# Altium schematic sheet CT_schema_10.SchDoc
size 278 x 170 mm
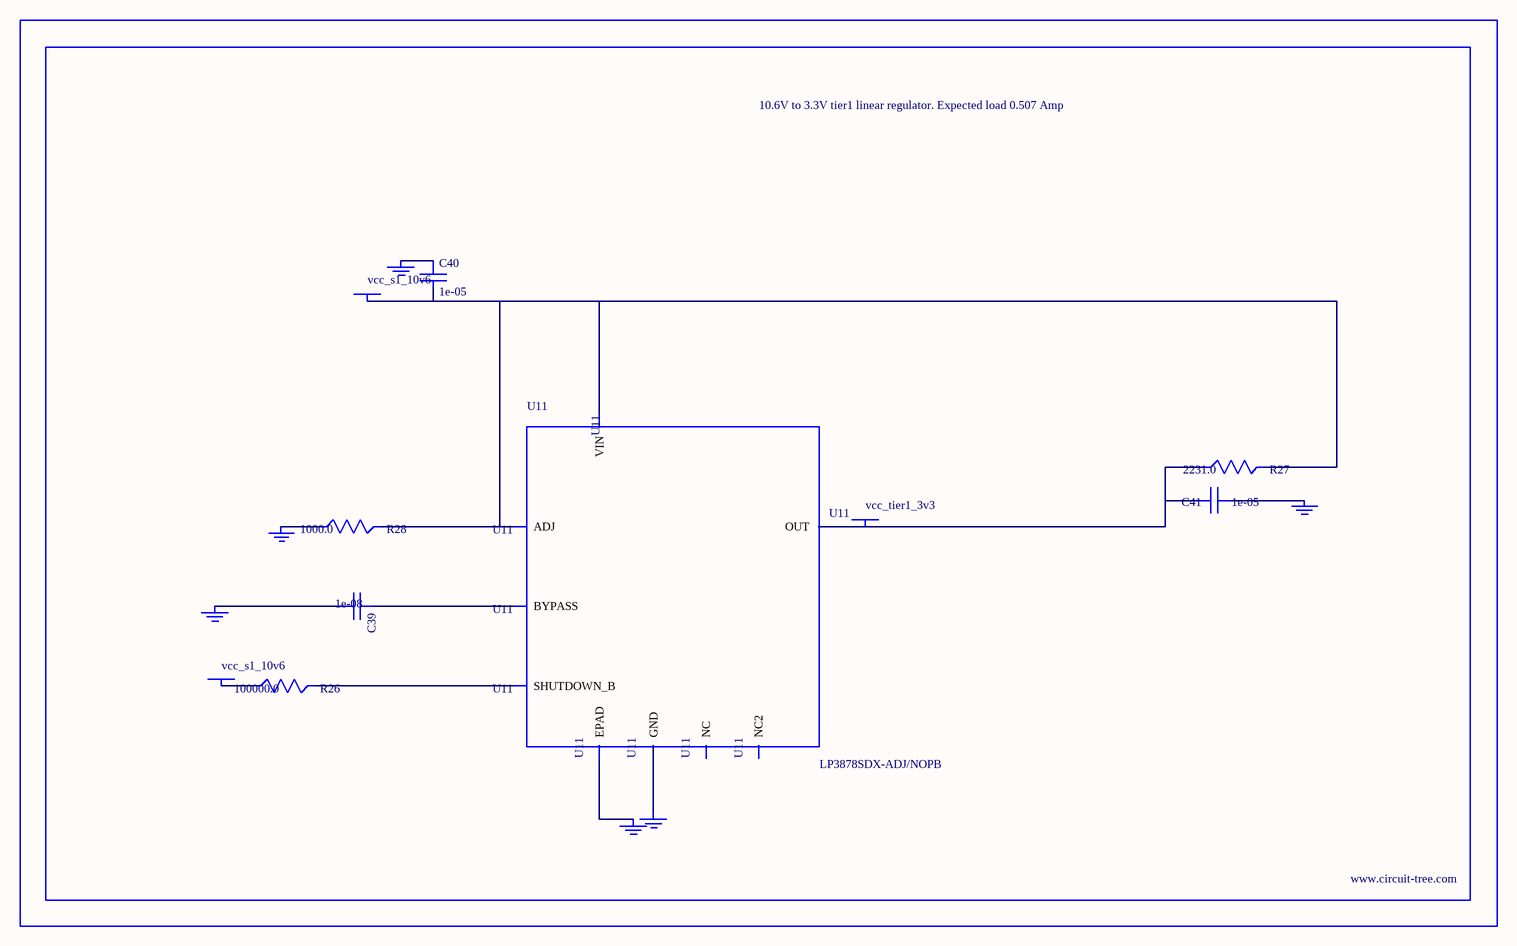
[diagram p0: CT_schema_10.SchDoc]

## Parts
BORDER9  (no value)
C39  1e-08  [C0402]
C40  1e-05  [C1206]
C41  1e-05  [C1210]
GND_INSTANCE_9_0  (no value)
GND_INSTANCE_9_1  (no value)
GND_INSTANCE_9_2  (no value)
GND_INSTANCE_9_3  (no value)
GND_INSTANCE_9_4  (no value)
GND_INSTANCE_9_5  (no value)
POWER_INSTANCE_9_0  vcc_s1_10v6
POWER_INSTANCE_9_1  vcc_s1_10v6
POWER_INSTANCE_9_2  vcc_tier1_3v3
R26  100000.0  [R0603]
R27  2231.0  [R0603]
R28  1000.0  [R0603]
U11  LP3878SDX-ADJ/NOPB  [WSON-8]

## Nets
NetC39_1: C39.1 U11.1(BYPASS)
NetC39_2: C39.2 GND_INSTANCE_9_0.0(GND)
NetC40_1: C40.1 GND_INSTANCE_9_1.0(GND)
NetC40_2: C40.2 POWER_INSTANCE_9_0.0(PWR) R27.2 R28.2 U11.4(VIN) U11.6(ADJ)
NetC41_1: C41.1 GND_INSTANCE_9_2.0(GND)
NetC41_2: C41.2 POWER_INSTANCE_9_2.0(PWR) R27.1 U11.5(OUT)
NetGND_INSTANCE_9_3_0: GND_INSTANCE_9_3.0(GND) R28.1
NetGND_INSTANCE_9_4_0: GND_INSTANCE_9_4.0(GND) U11.PAD(EPAD)
NetGND_INSTANCE_9_5_0: GND_INSTANCE_9_5.0(GND) U11.3(GND)
NetPOWER_INSTANCE_9_1_0: POWER_INSTANCE_9_1.0(PWR) R26.1
NetR26_2: R26.2 U11.8(SHUTDOWN_B)

Not connected (* = marked no-connect by the designer): U11 2(NC) 7(NC2)

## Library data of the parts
BORDER9 = BORDER_PAGE9
C39 = C0402C103K3RAC
C40 = C1206C106K3RACTU
C41 = GRM32DR61E106MA12L
GND_INSTANCE_9_0-GND_INSTANCE_9_5 = GND
POWER_INSTANCE_9_0-POWER_INSTANCE_9_2 = PWR
R26 = RC0603JR-07100KL
R27 = R27
R28 = RC0603JR-071KL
